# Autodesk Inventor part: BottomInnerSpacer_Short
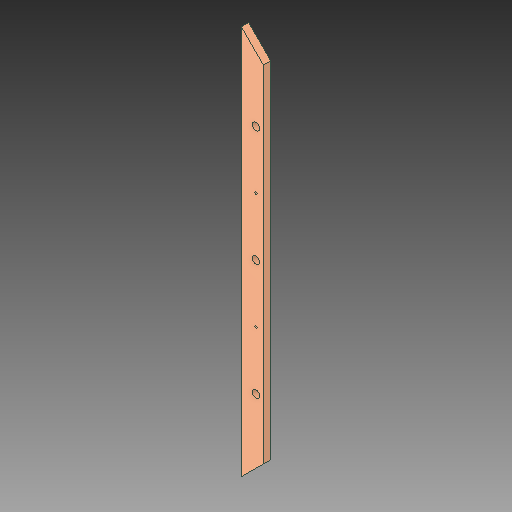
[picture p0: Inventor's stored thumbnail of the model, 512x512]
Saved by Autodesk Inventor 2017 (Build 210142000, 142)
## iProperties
Created: 2017-05
Part Number: BottomInnerSpacer_Short
Material: Generic
Document SubType Name: Modeling
Designer: Savy
Density: 1 g/cm^3
Appearance: Default
Author: Savy
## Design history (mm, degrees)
feature "SOLID1"
body "Solid1"
